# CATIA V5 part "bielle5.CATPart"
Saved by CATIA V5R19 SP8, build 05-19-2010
Part number: Pièce5
Bounding box of the stored display mesh (mm): x -60 to 0, y -12.449 to 147.156, z -147.15 to 12.455
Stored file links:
  G:\EU_thinkMotion\CFAO_2010\SIL_groupe1\SIL_groupe1\A reprendre\lalpha\lalpha\Alpha.mécanisme\bielle5.CATPart
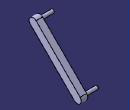
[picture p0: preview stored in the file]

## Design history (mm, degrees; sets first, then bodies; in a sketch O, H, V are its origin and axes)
Body1 (main body)
  Line1: stored without definition
  Line2: stored without definition
  Sketch1 on Line1, origin (-20, 0, 0), H (0, 0.7071, -0.7071), V (0, 0.7071, 0.7071)
    point P1 (0, -12.4958)
    line L1 (0, -12.4958) -> (190.495, -12.4958)
    line L2 (190.495, 12.5042) -> (0, 12.5042)
    arc A1 centre (190.495, 0.0042) radius 12.5 from (190.495, -12.4958) to (190.495, 12.5042) ccw
    point P6 (202.995, 0)
    arc A2 centre (0, 0.0042) radius 12.5 from (0, 12.5042) to (0, -12.4958) ccw
    coincidence: P1 V, A1 P6, P6 H
    horizontal: L1 H, L2 H
    tangency: A1 L1, A2 L2
  Pad1: profile Sketch1, direction (1, 0, 0), length 20
  Line3: stored without definition
  Line4: stored without definition
  Sketch2 on Line3, origin (-20, 0, 0), H (0, 0.7071, -0.7071), V (0, 0.7071, 0.7071)
    circle A1 centre (190.1302, 0) radius 5
    point P1 (190.1302, 0)
    circle A2 centre (0, 0) radius 5
    coincidence: P1 H
  Pad2: profile Sketch2, direction (-1, 0, 0), length 40
  DatumCurve1 to DatumCurve3
  DatumSurface1
  DatumCurve4
  Sketch3 on face of DatumSurface1, origin (0, 594.7665, -594.7665), H (-1, 0, 0), V (0, 0.7071, 0.7071)
    point P1 (10.0124, 269.3175)
  Line5: stored without definition
  DatumSurface2
  Line6: type Angle, RefPoint Sketch3, Curve Line5, Start 0, End 183, Angle 0
  DatumSurface3
  Sketch4 on face of DatumSurface2, origin (0, 594.7665, -594.7665), H (-1, 0, 0), V (0, 0.7071, 0.7071)
    axis line L1 (10.065, 268.9279) -> (10.065, 293.7497)
    vertical: L1 V
  DatumSurface4
  DatumSurface5
  Plane1: type Offset, RefPlane DatumSurface5, Offset 10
